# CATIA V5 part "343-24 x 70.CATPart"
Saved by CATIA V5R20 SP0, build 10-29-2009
Part number: 343-24 x 70
Definition: NONE
Nomenclature: 343-24 x 70
Source: Unknown
Description: 343-24 x 70
Bounding box of the stored display mesh (mm): x 0 to 70, y -18 to 18, z -18 to 18
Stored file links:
  C:\Users\Utente\Desktop\IO LAVORO\3D X SITO CF\X SITO\343-348\343-24 x 70.CATPart
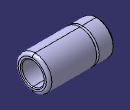
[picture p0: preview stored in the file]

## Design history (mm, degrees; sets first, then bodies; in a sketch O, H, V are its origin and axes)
Body1 "343-24 x 70" (main body)
  Solid1: solid without history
